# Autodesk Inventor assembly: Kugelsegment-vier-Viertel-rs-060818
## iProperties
Created: 2006-08
Part Number: Kugelsegment-vier-Viertel-rs-060818
Document SubType Name: Assembly
Designer: TB13 - rsc
Manufacturer: Standard
Standards Organization: Custom
Author: TB13 - rsc
